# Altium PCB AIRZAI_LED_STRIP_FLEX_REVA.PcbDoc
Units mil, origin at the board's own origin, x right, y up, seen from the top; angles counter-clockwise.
Board outline 6238.19 x 814.96 mil, 2 copper layers (Top Layer, Bottom Layer); 58 components, 62 nets, 290 pads, 0 vias.
Unrouted connection lines stored in the file: 83.
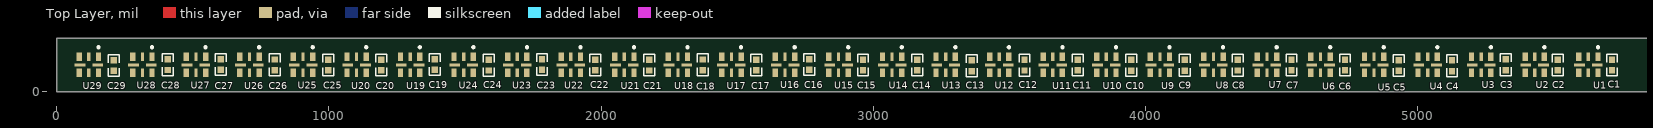
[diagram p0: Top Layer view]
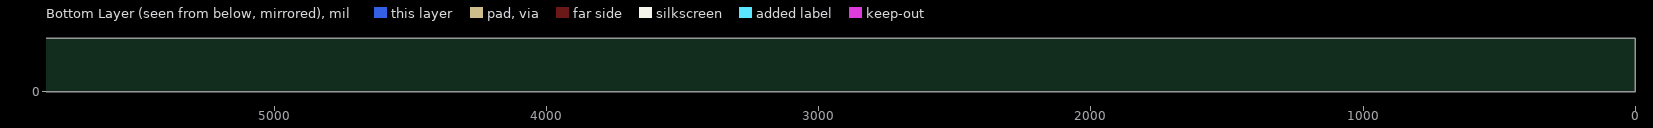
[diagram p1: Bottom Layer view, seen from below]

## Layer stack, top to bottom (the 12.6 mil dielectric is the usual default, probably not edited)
Top Solder: solder mask 0.4, Solder Resist, Dk 3.5
Top Layer: signal copper 1.4
Dielectric 1: dielectric 12.6, FR-4, Dk 4.8
Bottom Layer: signal copper 1.4
Bottom Solder: solder mask 0.4, Solder Resist, Dk 3.5

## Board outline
0,0 0,196.85 6213.15,196.85 cw(c6213.15,171.81) 6238.19,171.81 6238.19,-618.11 6139.76,-618.11 6139.76,-19.69 ccw(c6120.08,-19.69) 6120.08,0
board region "Layer Stack Region 2": 6139.76,-358 6139.76,-326 6238.19,-326 6238.19,-358
board region "Layer Stack Region 1": 6139.76,-326 6139.76,-19.69 6139.39,-15.84 6136.45,-8.75 6131.01,-3.32 6123.92,-0.38 6120.08,0 0,0 0,196.85 6213.15,196.85 6218.13,196.85 6227.33,193.04 6234.38,185.99 6238.19,176.79 6238.19,171.81 6238.19,-326
board region "Layer Stack Region 1": 6238.19,-358 6238.19,-618.11 6139.76,-618.11 6139.76,-358

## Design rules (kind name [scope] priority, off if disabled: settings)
Clearance Clearance_Board_Cutout_Electrodes [(InComponent('CRX0') OR InComponent('CRX1')) vs OnLayer('Multi-Layer')] p1: gap=0 ignorepadtopadclearanceinfootprint=FALSE
Clearance Clearance_Board_Cutout_Diodes [(InComponent('D1') OR InComponent('D2') OR InComponent('D3') OR InComponent('D4') OR InComponent('D5') OR InComponent('D6')) vs OnLayer('Multi-Layer')] p2: gap=0 ignorepadtopadclearanceinfootprint=FALSE
Clearance Clearance_Keepout [(OnLayer('Keep-Out Layer')) vs (InComponent('D1') OR InComponent('D2') OR InComponent('D3') OR InComponent('D4') OR InComponent('D5') OR InComponent('D6') OR InComponent('CRX0') OR InComponent('CRX1') OR InComponent('J1'))] p3: gap=0 ignorepadtopadclearanceinfootprint=FALSE
Clearance Clearance_GND_POLY_ELECTRODE [(InComponent('CRX0') OR InComponent('CRX1') OR InComponent('CRX2') OR InNet('NetCRX0_1') OR InNet('NetCRX1_1') OR InNet('NetCRX2_1') OR InNet('NetR4_2') OR InNet('NetR2_1') OR InNet('NetR1_1')) vs (InNet('GND') AND InPolygon)] p4: gap=30 ignorepadtopadclearanceinfootprint=FALSE
Clearance Clearance_POLYGON_KEEPOUT [(OnLayer('Keep-Out Layer')) vs (InNet('GND') AND InPolygon)] p5: gap=10 ignorepadtopadclearanceinfootprint=FALSE
Clearance Clearance_GND_POLY_REST [All vs (InNet('GND') AND InPolygon)] p6: gap=10 ignorepadtopadclearanceinfootprint=FALSE
Clearance [All] p7: gap=6 ignorepadtopadclearanceinfootprint=FALSE
MinimumSolderMaskSliver [All] p1: minsoldermaskwidth=1
PolygonConnect [All] p1: connectstyle=Direct reliefconductorwidth=10 reliefentries=4 polygonreliefangle="90 Angle" airgapwidth=10
RoomDefinition AIRZAI_LED_STRIP_FLEX_REVA [InComponentClass('AIRZAI_LED_STRIP_FLEX_REVA')] p1: confinementstyle=ConfineIn formatcopy=TRUE lockcomponents=FALSE outline -4184.14,-5126.44 10475.86,-5126.44 10475.86,4473.56 -4184.14,4473.56
RoutingVias [All] p1: holewidth=28 width=50 viastyle="Through Hole" minholewidth=8 minwidth=16 maxholewidth=28 maxwidth=50
SilkToSilkClearance [All] p1: silktosilkclearance=1
SilkToSolderMaskClearance [IsPad] p1: minsilkscreentomaskgap=2 clearancetoexposedcopper=TRUE
SolderMaskExpansion [All] p1: expansion=4
Width [All] p1: maxlimit=100 minlimit=6 preferedwidth=10
27 further rules are at their usual default settings.

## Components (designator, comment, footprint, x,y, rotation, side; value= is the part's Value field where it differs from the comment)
C1 "0.1µF" 0402CAP 5716,98.43 r270 top
C2 "0.1µF" 0402CAP 5517.17,98.43 r270 top
C3 "0.1µF" 0402CAP 5325.3,99.11 r270 top
C4 "0.1µF" 0402CAP 5127.94,95.43 r270 top
C5 "0.1µF" 0402CAP 4931.6,96.11 r270 top
C6 "0.1µF" 0402CAP 4734.75,98.43 r270 top
C7 "0.1µF" 0402CAP 4537.9,98.11 r270 top
C8 "0.1µF" 0402CAP 4341.05,97.46 r270 top
C9 "0.1µF" 0402CAP 4146.2,96.93 r270 top
C10 "0.1µF" 0402CAP 3948.35,97.11 r270 top
C11 "0.1µF" 0402CAP 3752.17,98.11 r270 top
C12 "0.1µF" 0402CAP 3556.65,97.61 r270 top
C13 "0.1µF" 0402CAP 3362.8,95.42 r270 top
C14 "0.1µF" 0402CAP 3162.43,98.11 r270 top
C15 "0.1µF" 0402CAP 2963,98.11 r270 top
C16 "0.1µF" 0402CAP 2765.62,99.64 r270 top
C17 "0.1µF" 0402CAP 2570.39,98.11 r270 top
C18 "0.1µF" 0402CAP 2373.54,98.64 r270 top
C19 "0.1µF" 0402CAP 1388.72,99.58 r270 top
C20 "0.1µF" 0402CAP 1191.44,98.11 r270 top
C21 "0.1µF" 0402CAP 2176.69,97.63 r270 top
C22 "0.1µF" 0402CAP 1979.09,97.74 r270 top
C23 "0.1µF" 0402CAP 1782.99,99.58 r270 top
C24 "0.1µF" 0402CAP 1587.14,97.58 r270 top
C25 "0.1µF" 0402CAP 997.87,97.9 r270 top
C26 "0.1µF" 0402CAP 800.06,98.65 r270 top
C27 "0.1µF" 0402CAP 602.32,99.95 r270 top
C28 "0.1µF" 0402CAP 406.72,99.43 r270 top
C29 "0.1µF" 0402CAP 208.62,96.46 r270 top
U1 "APA102-2020-256-8" APA102–2020 5629,98.43 r270 top
U2 "APA102-2020-256-8" APA102–2020 5432,98.43 r270 top
U3 "APA102-2020-256-8" APA102–2020 5235.3,98.43 r270 top
U4 "APA102-2020-256-8" APA102–2020 5038.45,98.43 r270 top
U5 "APA102-2020-256-8" APA102–2020 4841.6,98.43 r270 top
U6 "APA102-2020-256-8" APA102–2020 4644.75,98.43 r270 top
U7 "APA102-2020-256-8" APA102–2020 4447.9,98.43 r270 top
U8 "APA102-2020-256-8" APA102–2020 4251.05,98.43 r270 top
U9 "APA102-2020-256-8" APA102–2020 4054.2,98.43 r270 top
U10 "APA102-2020-256-8" APA102–2020 3857.35,98.43 r270 top
U11 "APA102-2020-256-8" APA102–2020 3660.5,98.43 r270 top
U12 "APA102-2020-256-8" APA102–2020 3463.65,98.43 r270 top
U13 "APA102-2020-256-8" APA102–2020 3266.8,98.43 r270 top
U14 "APA102-2020-256-8" APA102–2020 3070,98.43 r270 top
U15 "APA102-2020-256-8" APA102–2020 2873,98.43 r270 top
U16 "APA102-2020-256-8" APA102–2020 2676.24,98.43 r270 top
U17 "APA102-2020-256-8" APA102–2020 2479.39,98.43 r270 top
U18 "APA102-2020-256-8" APA102–2020 2282.54,98.43 r270 top
U19 "APA102-2020-256-8" APA102–2020 1298.29,98.43 r270 top
U20 "APA102-2020-256-8" APA102–2020 1101.44,98.43 r270 top
U21 "APA102-2020-256-8" APA102–2020 2085.69,98.43 r270 top
U22 "APA102-2020-256-8" APA102–2020 1888.84,98.43 r270 top
U23 "APA102-2020-256-8" APA102–2020 1691.99,98.43 r270 top
U24 "APA102-2020-256-8" APA102–2020 1495.14,98.43 r270 top
U25 "APA102-2020-256-8" APA102–2020 904.59,98.43 r270 top
U26 "APA102-2020-256-8" APA102–2020 707.74,98.43 r270 top
U27 "APA102-2020-256-8" APA102–2020 510.89,98.43 r270 top
U28 "APA102-2020-256-8" APA102–2020 314.04,98.43 r270 top
U29 "APA102-2020-256-8" APA102–2020 117.19,98.43 r270 top

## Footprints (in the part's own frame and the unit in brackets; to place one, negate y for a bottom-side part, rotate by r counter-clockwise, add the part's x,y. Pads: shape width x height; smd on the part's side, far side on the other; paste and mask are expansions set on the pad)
0402CAP [mm] "Chip Capacitor, Body 1.1x0.5mm, IPC High Density"
  rect 0.6x0.6 smd: 1(-0.5,0) 2(0.5,0)
  silkscreen extent -1.02,-0.51 1.02,0.51, body extent -0.5,-0.3 0.5,0.3, height 0.19
APA102–2020 [mm]
  rect 0.8x0.5 smd: 1(-0.75,0.9) 3(-0.75,-0.9) 4(0.75,-0.9) 6(0.75,0.9)
  rect 0.8x0.3 smd: 2(-0.75,0) 5(0.75,0)
  rect 0.3x1 smd: 7(0,-0.83) 8(0,0.83)
  silkscreen extent -1.7,0.85 -1.6,0.95, body extent -1,-1 1,1, height 0.94

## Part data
C1 C2 C3 C4 C5 C6 C7 C8 C9 C10 C11 C12 C13 C14 C15 C16 C17 C18 C19 C20 C21 C22 C23 C24 C25 C26 C27 C28 C29: library part C0402-100n, "Capacitor, X7R, ±10%", Case-EIA=0402, Case-Metric=1005, Manufacturer=TDK, Manufacturer Part Number=C1005X7R1C104K, Rated Voltage="16 V", Supplier Part Number 1=445-4952-2-ND, Tolerance=±20%
U1 U2 U3 U4 U5 U6 U7 U8 U9 U10 U11 U12 U13 U14 U15 U16 U17 U18 U19 U20 U21 U22 U23 U24 U25 U26 U27 U28 U29: "DotStar Micro LEDs", Package="SOIC-20 Adafruit Industries"

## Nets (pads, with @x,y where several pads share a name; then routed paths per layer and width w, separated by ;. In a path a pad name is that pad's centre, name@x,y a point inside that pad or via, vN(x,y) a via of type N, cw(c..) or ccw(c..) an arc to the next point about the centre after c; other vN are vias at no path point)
+5V: C1.1 C2.1 C3.1 C4.1 C5.1 C6.1 C7.1 C8.1 C9.1 C10.1 C11.1 C12.1 C13.1 C14.1 C15.1 C16.1 C17.1 C18.1 C19.1 C20.1 C21.1 C22.1 C23.1 C24.1 C25.1 C26.1 C27.1 C28.1 C29.1 U1.1 U1.8 U2.1 U2.8 U3.1 U3.8 U4.1 U4.8 U5.1 U5.8 U6.1 U6.8 U7.1 U7.8 U8.1 U8.8 U9.1 U9.8 U10.1 U10.8 U11.1 U11.8 U12.1 U12.8 U13.1 U13.8 U14.1 U14.8 U15.1 U15.8 U16.1 U16.8 U17.1 U17.8 U18.1 U18.8 U19.1 U19.8 U20.1 U20.8 U21.1 U21.8 U22.1 U22.8 U23.1 U23.8 U24.1 U24.8 U25.1 U25.8 U26.1 U26.8 U27.1 U27.8 U28.1 U28.8 U29.1 U29.8
GND: C1.2 C2.2 C3.2 C4.2 C5.2 C6.2 C7.2 C8.2 C9.2 C10.2 C11.2 C12.2 C13.2 C14.2 C15.2 C16.2 C17.2 C18.2 C19.2 C20.2 C21.2 C22.2 C23.2 C24.2 C25.2 C26.2 C27.2 C28.2 C29.2 U1.6 U1.7 U2.6 U2.7 U3.6 U3.7 U4.6 U4.7 U5.6 U5.7 U6.6 U6.7 U7.6 U7.7 U8.6 U8.7 U9.6 U9.7 U10.6 U10.7 U11.6 U11.7 U12.6 U12.7 U13.6 U13.7 U14.6 U14.7 U15.6 U15.7 U16.6 U16.7 U17.6 U17.7 U18.6 U18.7 U19.6 U19.7 U20.6 U20.7 U21.6 U21.7 U22.6 U22.7 U23.6 U23.7 U24.6 U24.7 U25.6 U25.7 U26.6 U26.7 U27.6 U27.7 U28.6 U28.7 U29.6 U29.7
LED_CLK_IN: U1.5
LED_CLK_OUT1: U1.2 U2.5
LED_CLK_OUT2: U2.2 U3.5
LED_CLK_OUT3: U3.2 U4.5
LED_CLK_OUT4: U4.2 U5.5
LED_CLK_OUT5: U5.2 U6.5
LED_CLK_OUT6: U6.2 U7.5
LED_CLK_OUT7: U7.2 U8.5
LED_CLK_OUT8: U8.2 U9.5
LED_CLK_OUT9: U9.2 U10.5
LED_CLK_OUT10: U10.2 U11.5
LED_CLK_OUT11: U11.2 U12.5
LED_CLK_OUT12: U12.2 U13.5
LED_CLK_OUT13: U13.2 U14.5
LED_CLK_OUT14: U14.2 U15.5
LED_CLK_OUT15: U15.2 U16.5
LED_CLK_OUT16: U16.2 U17.5
LED_CLK_OUT17: U17.2 U18.5
LED_CLK_OUT18: U18.2 U19.5
LED_CLK_OUT19: U19.2 U20.5
LED_CLK_OUT20: U20.2 U21.5
LED_CLK_OUT21: U21.2 U22.5
LED_CLK_OUT22: U22.2 U23.5
LED_CLK_OUT23: U23.2 U24.5
LED_CLK_OUT24: U24.3 U25.4
LED_CLK_OUT25: U25.2 U26.5
LED_CLK_OUT26: U26.2 U27.5
LED_CLK_OUT27: U27.2 U28.5
LED_CLK_OUT28: U28.2 U29.5
LED_CLK_OUT29: U29.2
LED_SDI: U1.4
LED_SDO_1: U1.3 U2.4
LED_SDO_2: U2.3 U3.4
LED_SDO_3: U3.3 U4.4
LED_SDO_4: U4.3 U5.4
LED_SDO_5: U5.3 U6.4
LED_SDO_6: U6.3 U7.4
LED_SDO_7: U7.3 U8.4
LED_SDO_8: U8.3 U9.4
LED_SDO_9: U9.3 U10.4
LED_SDO_10: U10.3 U11.4
LED_SDO_11: U11.3 U12.4
LED_SDO_12: U12.3 U13.4
LED_SDO_13: U13.3 U14.4
LED_SDO_14: U14.3 U15.4
LED_SDO_15: U15.3 U16.4
LED_SDO_16: U16.3 U17.4
LED_SDO_17: U17.3 U18.4
LED_SDO_18: U18.3 U19.4
LED_SDO_19: U19.3 U20.4
LED_SDO_20: U20.3 U21.4
LED_SDO_21: U21.3 U22.4
LED_SDO_22: U22.3 U23.4
LED_SDO_23: U23.3 U24.4
LED_SDO_24: U24.2 U25.5
LED_SDO_25: U25.3 U26.4
LED_SDO_26: U26.3 U27.4
LED_SDO_27: U27.3 U28.4
LED_SDO_28: U28.3 U29.4
LED_SDO_29: U29.3

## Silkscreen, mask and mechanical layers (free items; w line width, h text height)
Mechanical 1:
  lines w5: 1,98 cw(c1.43,98) 1.43,98.43 5805.12,98.43 5805.12,196.85 ; 117.19,88.93 117.19,107.93 ; 314.04,88.93 314.04,107.93 ; 510.89,88.93 510.89,107.93 ; 707.74,88.93 707.74,107.93 ; 904.59,88.93 904.59,107.93 ; 1101.44,88.93 1101.44,107.93 ; 1298.29,88.93 1298.29,107.93 ; 1495.14,88.93 1495.14,107.93 ; 1691.99,88.93 1691.99,107.93 ; 1888.84,88.93 1888.84,107.93 ; 2085.69,88.93 2085.69,107.93 ; 2282.54,88.93 2282.54,107.93 ; 2479.39,88.93 2479.39,107.93 ; 2676.24,88.93 2676.24,107.93 ; 2873.09,88.93 2873.09,107.93 ; 3069.94,88.93 3069.94,107.93 ; 3266.8,88.93 3266.8,107.93 ; 3463.65,88.93 3463.65,107.93 ; 3660.5,88.93 3660.5,107.93 ; 3857.35,88.93 3857.35,107.93 ; 4054.2,88.93 4054.2,107.93 ; 4251.05,88.93 4251.05,107.93 ; 4447.9,88.93 4447.9,107.93 ; 4644.75,88.93 4644.75,107.93 ; 4841.6,88.93 4841.6,107.93 ; 5038.45,88.93 5038.45,107.93 ; 5235.3,88.93 5235.3,107.93 ; 5432.15,88.93 5432.15,107.93 ; 5977.06,-342.52 6238.19,-342.52 ; 6139.76,145 6139.76,196.85 ; 5629,88.93 5629,107.93 ; 5629,88.93 5629,107.93 ; 5629,88.93 5629,107.93 ; 5629,88.93 5629,107.93
Mechanical 4:
  lines w5: 6120.08,0 cw(c6120.08,-19.69) 6139.76,-19.69 6139.76,-618.11 6238.19,-618.11 6238.19,171.81 ccw(c6213.15,171.81) 6213.15,196.85 6139.76,196.85 5805.12,196.85 0,196.85 0,0 6120.08,0 ; 6120.08,0 6120.08,0
Drill Drawing:
  text "PWB, LED STRIP FLEX" at 7277.47,-4374.31 h157.48
  text "PWB-020218-001" at 7464.48,-4700.1 h127.95
  text "1" at 9889.67,-4759.15 h78.74
  text "1" at 9700.7,-4763.09 h78.74
Mechanical 17:
  text "PWB, LED STRIP FLEX" at 7320.09,-4448.9 h157.48
  text "PWA-020218-001" at 7514.09,-4739.9 h127.95
  text "1" at 9692.82,-4751.28 h59.06
  text "1" at 9881.8,-4751.28 h59.06
  text "NOTES: /  / 1. ALL ASSEMBLY MATERIALS TO BE RoHS COMPLIANT. /  / 2. MATERIAL: /           • FLEXIBLE METAL CLAD DIELECTRIC IAW                 /             IPC-4204/11 E1E2 O0/0 CU W7 T/T /           • STIFFENER IAW IPC-4203/1-E1E8M1 /  / 3. FINISH:  IMMERSION GOLD /  / ALL EXPOSED CONDUCTIVE PATTERN AREAS NOT COVERED WITH COVERLAY MATERIAL OR OTHER PLATING  / SHALL BE IMMERSION GOLD (0.000030-0.000090 mm) OVER ELECTROLESS NICKEL (0.001-0.006 mm). /  / 4. LEGEND SHALL BE WHITE, PERMANENT, ORGANIC, NON-CONDUCTIVE UV OR EPOXY TYPE INK APPLIED  / TO THE TOP SIDE OF THE BOARD. THERE SHALL BE NO LEGEND ON ANY SOLDERABLE COMPONENT LAND. /  / 5. ALL ASSEMBLY MATERIALS TO BE RoHS COMPLIANT. /  / 6. ANY LABELS OR COMPOSITION OF, APPLIED TO THE BOARD NEED TO BE APPROVIED BY AIRZAI /  / 7. MINIMUM TRACE WIDTHS: /           EXTERNAL: 0.203 mm  INTERNAL: N/A /  / 8. MINIMUM SPACE BETWEEN FEATURES: /          EXTERNAL: 0.15 mm  INTERNAL: N/A /  / 9. Overall Board Thickness: 0.3mm" at -3994,-4847 h78.74
Mechanical 18:
  lines w5: -4414.86,-2617.22 -4214.86,-2617.22 ; -4414.86,-242.22 -4214.86,-242.22 ; -4414.86,2132.78 -4214.86,2132.78 ; -1914.86,-4992.22 -1914.86,-4792.22 ; -1914.86,4307.78 -1914.86,4507.78 ; 585.14,-4992.22 585.14,-4792.22 ; 585.14,4307.78 585.14,4507.78 ; 3085.14,-4992.22 3085.14,-4792.22 ; 3085.14,4307.78 3085.14,4507.78 ; 5585.14,-4992.22 5585.14,-4792.22 ; 5585.14,4307.78 5585.14,4507.78 ; 5884.35,-4494.44 10384.35,-4494.44 ; 5884.35,-4252.7 6955.02,-4252.7 ; 5884.35,-4018.65 6955.02,-4018.65 ; 5884.35,-3807.82 6955.02,-3807.82 ; 5885.14,-4792.22 10385.14,-4792.22 ; 6510.14,-4795.42 6510.14,-3595.42 ; 6955.02,-4794.44 6955.02,-3594.44 ; 6955.02,-4127.51 10384.2,-4127.51 ; 7294.98,-3594.44 10384.35,-3594.44 ; 7384.35,-3594.44 5884.35,-3594.44 ; 8085.14,-4992.22 8085.14,-4792.22 ; 8085.14,4307.78 8085.14,4507.78 ; 10007.97,-4794.44 10007.97,-4494.44 ; 10385.14,-3592.22 10385.14,-4792.22 ; 10385.14,-2617.22 10585.14,-2617.22 ; 10385.14,2132.78 10585.14,2132.78 ; 4484.35,-4794.44 5884.35,-4794.44 ; 4484.35,-4794.44 5884.35,-4794.44 ; 4484.35,-4794.44 4484.35,-3594.44 5884.35,-3594.44 ; 5884.35,-4794.44 10384.35,-4794.44 ; 5884.35,-4794.44 10384.35,-4794.44 ; 5884.35,-4794.44 5884.35,-3594.44 ; 10384.35,-4794.44 10384.35,-3594.44 ; 10384.35,-4794.44 10384.35,-3594.44 ; 10385.14,-4792.22 10385.14,4307.78 -4214.86,4307.78 -4214.86,-4792.22 10385.14,-4792.22 ; -4414.86,-4992.22 -4414.86,4507.78 10585.14,4507.78 10585.14,-4992.22 -4414.86,-4992.22
  text "1" at -3183.52,4377.78 h70
  text "2" at -687.86,4377.78 h70
  text "3" at 1801.49,4377.78 h70
  text "4" at 4308.16,4377.78 h70
  text "5" at 6807.14,4377.78 h70
  text "6" at 9312.14,4377.78 h70
  text "A" at -4339.86,3234.78 h70
  text "A" at 10460.14,3234.78 h70
  text "B" at -4339.86,854.78 h70
  text "B" at 10460.14,854.78 h70
  text "C" at -4339.86,-1520.22 h70
  text "C" at 10460.14,-1520.22 h70
  text "AIRZAI PROPRIETARY & CONFIDENTIAL" at 6040.27,-3483.56 h127.95
  text "DATE:" at 6540.65,-3656.64 h45
  text "ENGINEER:" at 5906.79,-3662.94 h45
  text "UNLESS OTHERWISE SPECIFIED" at 4583.96,-3723.57 h59.06
  text "21/01/19" at 6547.98,-3765.25 h59.06
  text "FD" at 6099.66,-3771.52 h78.74
  text "DIMENSIONS ARE IN MM" at 4706,-3849.55 h59.06
  text "PCB DESIGNER:" at 5902.85,-3871.33 h45
  text "DATE:" at 6528.84,-3873.18 h45
  text "D" at -4339.86,-3890.22 h70
  text "D" at 10460.14,-3890.22 h70
  text "AIRZAI" at 7245.97,-3928.44 h127.95
  text "TOLERANCES" at 4906.79,-3975.54 h59.06
  text "21/01/19" at 6547.98,-3979.82 h59.06
  text "DFM" at 6073.29,-3981.4 h78.74
  text "DATE:" at 6528.84,-4085.77 h45
  text "CHECK" at 5902.85,-4087.86 h45
  text "ANGULAR" at 5391.04,-4133.02 h59.06
  text "DECIMALS" at 4587.89,-4144.83 h59.06
  text "TITLE:" at 7006.8,-4191.24 h45
  text "FD" at 6139.03,-4204.59 h78.74
  text ".XX +/- .127MM" at 4540.65,-4302.31 h59.06
  text "+/-" at 5379.23,-4306.25 h59.06
  text "REL" at 5914.66,-4318.85 h45
  text "DATE:" at 6544.59,-4325.93 h45
  text "FD" at 6129.19,-4421.13 h78.74
  text ".XXX +/- .080MM" at 4528.84,-4463.73 h59.06
  text "REV:" at 10030.41,-4558.22 h45
  text "SCALE:" at 6550.1,-4559 h45
  text "DWG NO:" at 7001.28,-4566.88 h45
  text "SIZE" at 5914.66,-4570.03 h45
  text "B" at 6118.4,-4700.62 h120
  text "DO NOT SCALE DRAWING" at 4583.96,-4703.88 h70.87
  text "A" at 10114.08,-4719.78 h120
  text "1:1" at 6598.72,-4724.24 h120
  text "SHEET" at 9465.85,-4755.85 h45
  text "OF" at 9729.62,-4755.85 h45
  text "1" at -3183.52,-4922.22 h70
  text "2" at -687.86,-4922.22 h70
  text "3" at 1801.49,-4922.22 h70
  text "4" at 4308.16,-4922.22 h70
  text "5" at 6807.14,-4922.22 h70
  text "6" at 9312.14,-4922.22 h70

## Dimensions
5805.12,322 to 6139.76,196.85 on Mechanical 1
0,196.85 to 5805.12,196.85 on Mechanical 1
